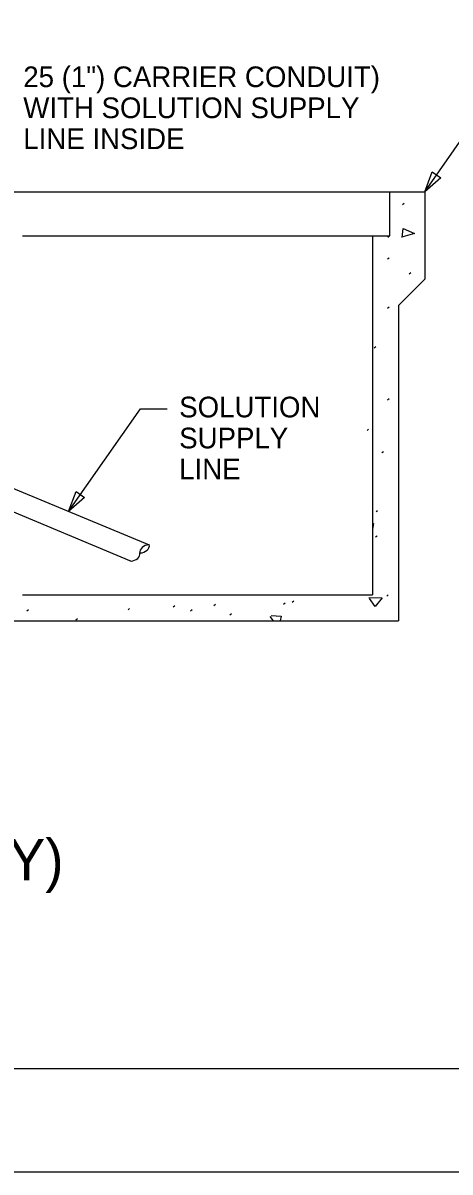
# Model space of a CAD drawing. Extents: x 3239 to 4230, y -4276 to -2494.
# Drawn here: x 3609.7 to 3671.7, y -4276.3 to -4109.5 of the extents above; entities that cross this region are included whole.
import ezdxf

# ---------------------------------------------------------------- set-up
doc = ezdxf.new("R2010")
doc.units = 0
doc.layers.add('2', color=7, linetype='Continuous')
doc.layers.add('PLT-BNDY', color=7, linetype='Continuous')

msp = doc.modelspace()

# ---------------------------------------------------------------- linework, layer by layer
at = {"layer": '2'}
for p, q in [((3607.1, -4133.99), (3662.9, -4133.99)), ((3662.9, -4133.99), (3668, -4133.99)), ((3662.9, -4133.99), (3662.9, -4139.09)), ((3668, -4133.99), (3668, -4146.69)), ((3664.77, -4135.85), (3665, -4135.66)), ((3515.24, -4138.67), (3628.01, -4185.23)), ((3662.9, -4139.09), (3662.9, -4140.39)), ((3514.18, -4141.2), (3625.36, -4187.61)), ((3609.6, -4140.39), (3660.4, -4140.39)), ((3660.4, -4140.39), (3662.9, -4140.39)), ((3660.4, -4140.39), (3660.4, -4192.49)), ((3662.65, -4140.58), (3662.88, -4140.39)), ((3662.6, -4143.75), (3662.83, -4143.56)), ((3665.76, -4145.91), (3665.99, -4145.73)), ((3668, -4146.69), (3664.2, -4150.49)), ((3662.58, -4150.9), (3662.82, -4150.71)), ((3664.2, -4150.49), (3664.2, -4196.29)), ((3660.67, -4156.66), (3660.9, -4156.47)), ((3662.61, -4164.2), (3662.84, -4164.01)), ((3659.66, -4168.63), (3659.85, -4168.44)), ((3661.79, -4171.86), (3662.02, -4171.68)), ((3660.94, -4180.42), (3661.17, -4180.24)), ((3660.84, -4184.1), (3661.08, -4183.92)), ((3609.6, -4192.49), (3660.4, -4192.49)), ((3662.48, -4192.68), (3662.71, -4192.49)), ((3610.24, -4194.83), (3610.47, -4194.64)), ((3624.92, -4194.68), (3625.15, -4194.5)), ((3631.47, -4194.24), (3631.7, -4194.05)), ((3633.97, -4194.83), (3634.21, -4194.64)), ((3637.38, -4194.05), (3637.62, -4193.87)), ((3647.52, -4193.84), (3647.75, -4193.66)), ((3648.78, -4193.56), (3649.01, -4193.38)), ((3605.8, -4196.29), (3664.2, -4196.29)), ((3617.34, -4196.14), (3617.58, -4195.95)), ((3639.71, -4195.39), (3639.94, -4195.2)), ((4065.03, -4261.29), (3279.03, -4261.29))]:
    msp.add_line(p, q, dxfattribs=at)
for points in [[(3668, -4133.99), (3674.42, -4124.84), (3678.96, -4124.84)], [(3664.73, -4140.65), (3664.87, -4139.3), (3666.5, -4140.04), (3664.84, -4140.53)], [(3616.28, -4180.39), (3626.75, -4165.52), (3630.58, -4165.52)], [(3660.4, -4182.15), (3660.58, -4182.16), (3660.4, -4182.96)], [(3659.87, -4192.91), (3661.81, -4192.93), (3660.83, -4194.19), (3660.01, -4193.05)], [(3646.03, -4196.29), (3645.56, -4195.65)], [(3645.7, -4195.51), (3647.16, -4195.58), (3647, -4196.29)]]:
    msp.add_lwpolyline(points, dxfattribs=at)
for points in [[(3670.34, -4131.96), (3668, -4133.99), (3669.11, -4131.1)], [(3618.62, -4178.37), (3616.28, -4180.39), (3617.39, -4177.5)]]:
    msp.add_lwpolyline(points, close=True, dxfattribs=at)
for centre, major_axis, start_param, end_param in [((3625.13, -4186.54), (-1.53, 0), 1.677447, 3.248243), ((3628.17, -4186.31), (1.53, 0), 1.677447, 3.248243), ((3626.49, -4185.35), (1.53, 0), 4.819039, 6.389836)]:
    msp.add_ellipse(centre, major_axis=major_axis, ratio=0.707981, start_param=start_param, end_param=end_param, dxfattribs=at)
at = {"layer": 'PLT-BNDY'}
msp.add_lwpolyline([(3239.03, -3682.29), (4080.03, -3682.29), (4080.03, -4276.29), (3239.03, -4276.29)], close=True, dxfattribs=at)

# ---------------------------------------------------------------- texts
at = {"layer": '2'}
for s, height, p in [('25 (1") CARRIER CONDUIT)', 3, (3609.71, -4118.8)), ('WITH SOLUTION SUPPLY', 3, (3609.71, -4123.3)), ('LINE INSIDE', 3, (3609.71, -4127.8)), ('SOLUTION', 3, (3632.35, -4166.74)), ('SUPPLY', 3, (3632.35, -4171.24)), ('LINE', 3, (3632.35, -4175.74)), ('(SPRAY DISK INSTALLED CONCURRENTLY WITH NEW BITUMINOUS OVERLAY)', 6, (3310.63, -4233.97))]:
    msp.add_text(s, height=height, dxfattribs=at).set_placement(p)

doc.saveas('drawing.dxf')
